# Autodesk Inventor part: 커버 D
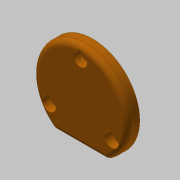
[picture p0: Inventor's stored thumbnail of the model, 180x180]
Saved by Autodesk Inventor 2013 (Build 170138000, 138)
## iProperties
Created: 2020-04
Part Number: 커버 D
Material: 알루미늄 6061
Document SubType Name: Modeling
Designer: mduedu
Density: 2.71 g/cm^3
Mass: 32.8423 g
Surface Area: 61.5912 cm^2
Volume: 12.1189 cm^3
Author: mduedu
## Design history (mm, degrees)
sketch "스케치1"
  geometry: C1 r 26 at (0, 0); 1 further point
  constraints: 1 centre point, 1 coincident
  dimensions: "d0" = 52 diameter of C1
extrude "돌출1" new body sketch "스케치1" distance "d1" = 7; taper "d2" = 0 deg
sketch "스케치2"
  geometry: L1 (-14.62, -21.5)-(14.62, -21.5); A1 r 26 centre (0, 0) between (-14.62, -21.5) and (14.62, -21.5) reference; 1 further point
  constraints: 2 end point, 2 point on circle, 1 horizontal
  dimensions: "d3" = 21.5 distance from line of L1 point (0, 0)
extrude "돌출2" cut sketch "스케치2" stored distance "d4" = 7; taper "d5" = 0 deg
fillet "모깎기1" dims "d6" = 3
fillet "모깎기2" dims "d7" = 3
sketch "스케치3" dims "d8" = 40
  geometry: 3 further points
  constraints: 2 vertical alignment, 1 coincident, 2 other
hole "구멍1" sketch "스케치3" at (0, 20) diameter "d9" = 4.5; stored, may be unused: countersink angle "d13" = 90 deg, drill point angle "d15" = 118 deg; dims "d10" = 6, "d11" = 8, "d12" = 4.4, "d14" = 8
sketch "스케치4"
  geometry: C1 r 14 at (0, 0); 1 further point
  constraints: 1 centre point, 1 coincident
  dimensions: "d19" = 28 diameter of C1
extrude "돌출3" join sketch "스케치4" distance "d20" = 4; taper "d21" = 0 deg
sketch "스케치5"
  geometry: C1 r 12 at (0, 0); 1 further point
  constraints: 1 centre point, 1 coincident
  dimensions: "d22" = 24 diameter of C1
extrude "돌출4" cut sketch "스케치5" distance "d23" = 8; taper "d24" = 0 deg
fillet "모깎기3" dims "d25" = 3
chamfer "모따기1" distance "d26" = 0.5; stored, may be unused: second distance "d27" = 2, angle "d28" = 45 deg
node "솔리드1"
pattern_circular "원형 패턴1" dims angle "d17" = 360 deg
node "투영된 루프1"
